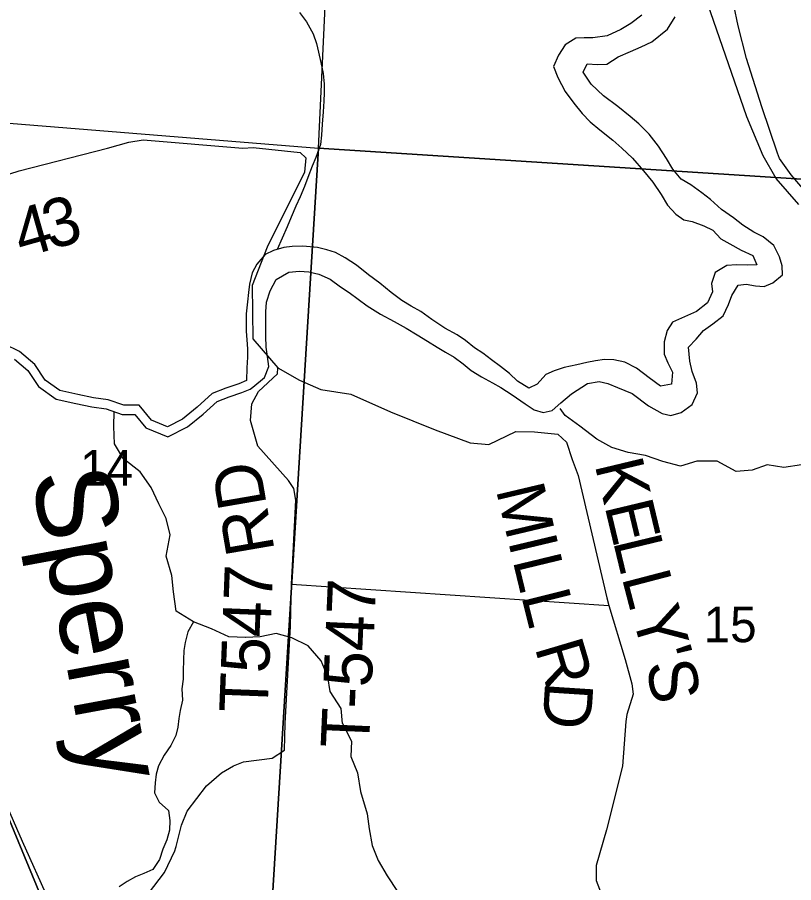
# Model space of a CAD drawing. Extents: x 0 to 82.7, y -0.2 to 22.
# Drawn here: x 3.348 to 4.26, y 16.567 to 17.584 of the extents above; entities that cross this region are included whole.
import ezdxf

# ---------------------------------------------------------------- set-up
doc = ezdxf.new("R2010")
doc.units = 0
for name, color, linetype in [('GM_X_County_Road', 7, 'Continuous'), ('GM_X_County_Road_Text', 7, 'Continuous'), ('GM_X_Minor_River', 7, 'Continuous'), ('GM_X_Minor_River_Text', 7, 'Continuous'), ('GM_X_Rail_Line', 7, 'Continuous'), ('GM_X_Section', 7, 'Continuous'), ('GM_X_Section_Text', 7, 'Continuous'), ('GM_X_State_Route', 7, 'Continuous'), ('GM_X_Township_Road', 7, 'Continuous'), ('GM_X_Township_Road_Text', 7, 'Continuous'), ('GM_X_Township_Text', 7, 'Continuous'), ('SH_Cut_Line', 7, 'Continuous')]:
    doc.layers.add(name, color=color, linetype=linetype)

msp = doc.modelspace()

# ---------------------------------------------------------------- linework, layer by layer
at = {"layer": 'GM_X_County_Road'}
for points in [[(3.3096, 17.3905), (3.3503, 17.4035), (3.454, 17.4299), (3.479, 17.4369), (3.4961, 17.4398), (3.6132, 17.4301), (3.6251, 17.4309), (3.6804, 17.4248), (3.6869, 17.4187), (3.6854, 17.4016), (3.6418, 17.3136), (3.624, 17.2688), (3.6248, 17.2062), (3.6543, 17.1721), (3.6797, 17.1577), (3.7047, 17.1467), (3.74, 17.141), (3.7866, 17.1205), (3.8389, 17.0993), (3.8802, 17.0841), (3.9018, 17.0818), (3.9336, 17.0974), (3.9556, 17.097), (3.9828, 17.094), (3.993, 17.0848), (3.9999, 17.0645), (4.0068, 17.0456), (4.0407, 16.9017)], [(4.0407, 16.9017), (4.0428, 16.893), (4.0621, 16.8294), (4.0699, 16.8008), (4.0713, 16.7889), (4.064, 16.765), (4.0629, 16.7567), (4.0589, 16.7041), (4.0403, 16.6296), (4.0279, 16.5877), (4.0281, 16.5698), (4.0357, 16.5496)]]:
    msp.add_lwpolyline(points, dxfattribs=at)
at = {"layer": 'GM_X_Minor_River'}
for points in [[(3.6796, 17.5893), (3.6879, 17.5782), (3.6958, 17.5641), (3.6996, 17.553), (3.7018, 17.5427), (3.7047, 17.5306), (3.7073, 17.5176), (3.7087, 17.5051), (3.7087, 17.4948), (3.7082, 17.4853), (3.7074, 17.4728), (3.7061, 17.458), (3.7053, 17.4451), (3.7041, 17.4341), (3.6987, 17.4189), (3.6944, 17.4087), (3.6894, 17.3954), (3.6855, 17.3848), (3.6805, 17.3727), (3.6751, 17.3617), (3.67, 17.3488), (3.665, 17.3374), (3.6592, 17.3242), (3.6532, 17.3111)], [(4.0818, 17.5863), (4.0689, 17.5764), (4.0571, 17.5692), (4.0408, 17.562), (4.024, 17.5597), (4.0138, 17.5597), (4.0043, 17.559), (3.9917, 17.5514), (3.9837, 17.5392), (3.978, 17.5259), (3.983, 17.513), (3.9917, 17.4967), (4.0016, 17.483), (4.0114, 17.4708), (4.0209, 17.4609), (4.0323, 17.4514), (4.0475, 17.4392), (4.0582, 17.4301), (4.0707, 17.4183), (4.0836, 17.4035), (4.0946, 17.3901), (4.1045, 17.3757), (4.1117, 17.3631), (4.1216, 17.3525), (4.1311, 17.346), (4.1406, 17.3437), (4.1546, 17.3388), (4.1649, 17.3335), (4.1744, 17.3236), (4.185, 17.3175), (4.1983, 17.3102), (4.212, 17.3038), (4.2166, 17.2931), (4.2055, 17.2927), (4.193, 17.2928), (4.1816, 17.292), (4.1679, 17.284), (4.1633, 17.2711), (4.1648, 17.2612), (4.1588, 17.2483), (4.1458, 17.2381), (4.1318, 17.232), (4.1177, 17.2255), (4.1112, 17.2157), (4.1078, 17.2027), (4.1078, 17.1879), (4.1123, 17.178), (4.1177, 17.167), (4.1165, 17.1529), (4.1036, 17.1503), (4.0903, 17.1602), (4.0755, 17.1716), (4.0618, 17.1785), (4.0489, 17.1815), (4.0378, 17.1819), (4.0272, 17.1804), (4.0169, 17.1781), (4.0052, 17.1755), (3.9903, 17.1724), (3.9785, 17.1683), (3.9687, 17.1641), (3.9588, 17.1527)], [(4.1366, 17.1961), (4.1454, 17.2056), (4.1541, 17.2159), (4.1651, 17.2235), (4.1773, 17.233), (4.1834, 17.2463), (4.1872, 17.2569), (4.1948, 17.2691), (4.2043, 17.2702), (4.215, 17.2683), (4.2252, 17.2675), (4.2355, 17.2717), (4.2469, 17.2812), (4.2465, 17.2918), (4.2435, 17.3025), (4.2367, 17.3158), (4.2241, 17.3257), (4.2131, 17.3314), (4.2002, 17.3394), (4.1892, 17.3481), (4.1751, 17.358), (4.1622, 17.3698), (4.152, 17.3774), (4.139, 17.387), (4.128, 17.3934), (4.1181, 17.4052), (4.1106, 17.4178), (4.1011, 17.4322), (4.0904, 17.4463), (4.0783, 17.4585), (4.068, 17.4672), (4.0536, 17.479), (4.0365, 17.4916), (4.0221, 17.5053), (4.0129, 17.5193), (4.0175, 17.5292), (4.0297, 17.5284), (4.0407, 17.5288), (4.054, 17.5372), (4.0684, 17.5436), (4.081, 17.5489), (4.0932, 17.555), (4.1118, 17.5698), (4.1209, 17.5842)], [(3.9588, 17.1527), (3.9489, 17.1481), (3.9356, 17.1565), (3.9261, 17.1653), (3.9158, 17.1736), (3.9052, 17.1813), (3.8949, 17.1892), (3.8851, 17.1953), (3.8744, 17.2041), (3.8646, 17.2106), (3.8501, 17.2186), (3.8349, 17.2288), (3.822, 17.2383), (3.8106, 17.2444), (3.7996, 17.2509), (3.7871, 17.2604), (3.7738, 17.2715), (3.7608, 17.2813), (3.7464, 17.2924), (3.7331, 17.3011), (3.7217, 17.3076), (3.7118, 17.3107), (3.7008, 17.3133), (3.6837, 17.3149), (3.6708, 17.3145), (3.6613, 17.3134), (3.6491, 17.3099), (3.6392, 17.305), (3.6293, 17.2936), (3.624, 17.2834), (3.621, 17.2704), (3.6198, 17.2606), (3.6187, 17.2495), (3.6171, 17.2355), (3.6171, 17.215), (3.6179, 17.2047), (3.6186, 17.1944), (3.6186, 17.1845), (3.6179, 17.172), (3.6172, 17.157)], [(3.6215, 17.1471), (3.6246, 17.1494), (3.6383, 17.1605), (3.6437, 17.1734), (3.6421, 17.1855), (3.6403, 17.1962), (3.6399, 17.2091), (3.6399, 17.2376), (3.641, 17.249), (3.6452, 17.2623), (3.6521, 17.2756), (3.6669, 17.2843), (3.6795, 17.2855), (3.6905, 17.2847), (3.7023, 17.282), (3.7156, 17.2763), (3.7277, 17.2672), (3.738, 17.2603), (3.7486, 17.2527), (3.7589, 17.2447), (3.7748, 17.2352), (3.7908, 17.2265), (3.8048, 17.2185), (3.8178, 17.2109), (3.8299, 17.2032), (3.8413, 17.1964), (3.8512, 17.1903), (3.8611, 17.1846), (3.8717, 17.1766), (3.8812, 17.169), (3.8934, 17.1614), (3.9063, 17.1542), (3.9162, 17.1488), (3.9294, 17.1401), (3.9446, 17.1298), (3.9553, 17.1226), (3.9659, 17.1195), (3.9762, 17.1218), (3.9865, 17.1309), (3.999, 17.1415), (4.018, 17.1537), (4.0317, 17.1559), (4.0416, 17.1537), (4.053, 17.1491), (4.0701, 17.1418), (4.0895, 17.1274), (4.1054, 17.1182), (4.1157, 17.116), (4.1278, 17.1194), (4.1408, 17.1289), (4.1469, 17.1425), (4.1457, 17.1539), (4.1408, 17.1676), (4.1381, 17.1798), (4.1366, 17.1961)], [(3.6172, 17.157), (3.6082, 17.1532), (3.5931, 17.1481), (3.5771, 17.1418), (3.5596, 17.1259), (3.5421, 17.1116), (3.5246, 17.1027), (3.5057, 17.1104), (3.4914, 17.128), (3.4732, 17.1281), (3.455, 17.1343), (3.4376, 17.1367), (3.4194, 17.1406), (3.3982, 17.1453), (3.3809, 17.1576), (3.3688, 17.1759), (3.3507, 17.1912), (3.3333, 17.1997)], [(3.3448, 17.1821), (3.3607, 17.1687), (3.3729, 17.15), (3.3938, 17.1353), (3.4171, 17.1301), (3.4357, 17.1261), (3.4525, 17.1237), (3.4714, 17.1173), (3.4862, 17.1172), (3.499, 17.1014), (3.5251, 17.0908), (3.548, 17.1026), (3.5666, 17.1177), (3.5829, 17.1324), (3.5968, 17.138), (3.612, 17.143), (3.6215, 17.1471)], [(3.616, 16.8555), (3.5967, 16.8561), (3.5763, 16.8654), (3.5551, 16.8739), (3.5347, 16.8862), (3.5318, 16.909), (3.5296, 16.928), (3.5229, 16.9508), (3.5276, 16.9758), (3.5232, 16.9949), (3.5142, 17.0124), (3.5052, 17.0314), (3.4924, 17.0497), (3.4728, 17.0651), (3.4623, 17.0826), (3.4617, 17.1031), (3.4618, 17.1206), (3.4618, 17.12)], [(4.2692, 17.0582), (4.2483, 17.0549), (4.229, 17.058), (4.2111, 17.0517), (4.1926, 17.0503), (4.1703, 17.0625), (4.1464, 17.0623), (4.127, 17.0567), (4.1062, 17.0621), (4.0861, 17.069), (4.0657, 17.0726), (4.0464, 17.0784), (4.0286, 17.0883), (4.009, 17.1036), (3.9916, 17.1162), (3.9856, 17.1241)], [(3.5551, 16.8739), (3.5483, 16.8621), (3.5453, 16.8496), (3.5437, 16.8402), (3.5433, 16.8292), (3.5428, 16.8159), (3.5428, 16.8064), (3.5416, 16.795), (3.5423, 16.7818), (3.5396, 16.7696), (3.538, 16.7602), (3.5368, 16.7499), (3.5345, 16.7401), (3.5284, 16.7284), (3.5208, 16.717), (3.5139, 16.7045), (3.5112, 16.6947), (3.51, 16.6845), (3.5092, 16.6727), (3.5148, 16.6621), (3.5257, 16.6521), (3.5275, 16.6404), (3.5271, 16.629), (3.5236, 16.6176), (3.5191, 16.6067), (3.5152, 16.5945), (3.5072, 16.5828), (3.4966, 16.5783), (3.4871, 16.5742), (3.4773, 16.5689), (3.4678, 16.5625)], [(3.7302, 16.7544), (3.7284, 16.7721), (3.7157, 16.7919), (3.7128, 16.809), (3.7049, 16.8281), (3.6899, 16.8456), (3.6706, 16.8548), (3.652, 16.8602), (3.6334, 16.8561), (3.616, 16.8555), (3.6164, 16.8559)], [(3.7302, 16.7544), (3.7405, 16.7336), (3.74, 16.7154), (3.7476, 16.6963), (3.7513, 16.6743), (3.7592, 16.6484), (3.7614, 16.6305), (3.7648, 16.6112), (3.7719, 16.5933), (3.7825, 16.5754), (3.7946, 16.5571)]]:
    msp.add_lwpolyline(points, dxfattribs=at)
at = {"layer": 'GM_X_Rail_Line'}
msp.add_lwpolyline([(4.266, 17.3638), (4.2395, 17.3944), (4.2242, 17.4209), (4.2049, 17.4668), (4.1341, 17.672)], dxfattribs=at)
at = {"layer": 'GM_X_Section'}
msp.add_lwpolyline([(3.7473, 18.3959), (3.7502, 18.459), (4.7658, 18.3936), (4.7026, 17.3656), (3.7019, 17.4301), (3.7258, 17.938)], dxfattribs=at)
for points in [[(2.9797, 17.4884), (3.7019, 17.4301), (3.6383, 16.3983), (3.4469, 16.4092), (3.3543, 16.6156), (3.1437, 17.0983)], [(3.7019, 17.4301), (4.7026, 17.3656), (4.6367, 16.3423), (3.6383, 16.3983)]]:
    msp.add_lwpolyline(points, close=True, dxfattribs=at)
at = {"layer": 'GM_X_State_Route'}
msp.add_lwpolyline([(4.2752, 17.3777), (4.2569, 17.3988), (4.2435, 17.4178), (4.2411, 17.4243), (4.2226, 17.4784), (4.2045, 17.5352), (4.1946, 17.5735), (4.1895, 17.598)], dxfattribs=at)
at = {"layer": 'GM_X_Township_Road'}
msp.add_line((3.6703, 16.9179), (4.0428, 16.893), dxfattribs=at)
for points in [[(3.6721, 16.9549), (3.6752, 17.0165), (3.6729, 17.0302), (3.6665, 17.0397), (3.6305, 17.0799), (3.6221, 17.1103), (3.6236, 17.1296), (3.6316, 17.1444), (3.6536, 17.1649), (3.6543, 17.1721)], [(3.5342, 16.6085), (3.5346, 16.61), (3.5409, 16.6349), (3.5478, 16.6512), (3.5702, 16.6812), (3.5881, 16.6963), (3.6021, 16.7047), (3.6139, 16.7092), (3.6476, 16.7136), (3.6618, 16.7229), (3.6626, 16.7544), (3.6689, 16.8686), (3.6703, 16.9179), (3.6721, 16.9549)], [(3.4073, 16.4755), (3.4373, 16.4734), (3.4536, 16.476), (3.4639, 16.4817), (3.4696, 16.4904), (3.4734, 16.5128), (3.4833, 16.528), (3.4959, 16.5466), (3.521, 16.5795), (3.5332, 16.6046), (3.5342, 16.6085)]]:
    msp.add_lwpolyline(points, dxfattribs=at)
at = {"layer": 'GM_X_Township_Text'}
msp.add_lwpolyline([(5.9672, 20.3493), (3.6288, 20.5056), (3.179, 20.5374), (2.884, 20.5583), (2.8651, 20.279), (2.8645, 20.2703), (2.8645, 20.2693), (2.8288, 19.7415), (2.7788, 19.0007), (2.7784, 18.9951), (2.7199, 18.1299), (3.0279, 17.3486), (3.0556, 17.2782), (3.2909, 16.7562), (3.4071, 16.476), (3.6125, 15.9807), (3.8036, 15.5496), (4.1209, 14.8338)], dxfattribs=at)
msp.add_lwpolyline([(2.1, 19.5964), (2.1, 14.1), (2.4652, 14.1), (3.1288, 14.3932), (3.6092, 14.6054), (3.7187, 14.6543), (4.1209, 14.8338), (3.8036, 15.5496), (3.6125, 15.9807), (3.4071, 16.476), (3.2909, 16.7562), (3.0556, 17.2782), (3.0279, 17.3486), (2.7199, 18.1299), (2.4438, 18.782), (2.397, 18.8926), (2.3145, 19.0873), (2.2742, 19.1826)], close=True, dxfattribs=at)
at = {"layer": 'SH_Cut_Line'}
for points in [[(4.1209, 14.8338), (3.8036, 15.5496), (3.6125, 15.9807), (3.4071, 16.476), (3.2909, 16.7562), (3.0556, 17.2782), (3.0279, 17.3486), (2.7199, 18.1299), (2.7784, 18.9951), (2.7788, 19.0007), (2.8288, 19.7415), (2.8645, 20.2693), (2.8645, 20.2703), (2.8651, 20.279), (2.884, 20.5583), (3.179, 20.5374), (3.6288, 20.5056), (5.9672, 20.3493), (5.9756, 20.3782), (6.1272, 20.9), (2.1, 20.9), (2.1, 14.1)], [(8.9, 14.1), (8.9, 20.9), (6.1272, 20.9), (5.9756, 20.3782), (5.9672, 20.3493), (3.6288, 20.5056), (3.179, 20.5374), (2.884, 20.5583), (2.8651, 20.279), (2.8645, 20.2703), (2.8645, 20.2693), (2.8288, 19.7415), (2.7788, 19.0007), (2.7784, 18.9951), (2.7199, 18.1299), (3.0279, 17.3486), (3.0556, 17.2782), (3.2909, 16.7562), (3.4071, 16.476), (3.6125, 15.9807), (3.8036, 15.5496), (4.1209, 14.8338)]]:
    msp.add_lwpolyline(points, dxfattribs=at)

# ---------------------------------------------------------------- texts
at = {"layer": 'GM_X_County_Road_Text'}
for s, rotation, p in [('3', 15.9617, (3.3871, 17.3104)), ('4', 15.8275, (3.3532, 17.3008)), ('K', 283.4743, (4.026, 17.0586)), ('M', 283.3313, (3.91, 17.0292)), ('E', 283.4692, (4.0376, 17.01)), ('I', 283.3898, (3.9243, 16.9691)), ('L', 283.583, (4.0476, 16.9685)), ('L', 283.5846, (3.9297, 16.9462)), ('L', 284.6517, (4.0578, 16.9261)), ('L', 284.1107, (3.9398, 16.9044)), ('Y', 286.3844, (4.0691, 16.8831)), ('R', 286.544, (3.9555, 16.8438)), ("'", 286.2757, (4.0832, 16.8352)), ('S', 280.6232, (4.0863, 16.8246)), ('D', 266.2854, (3.9682, 16.8043))]:
    msp.add_text(s, height=0.0568, rotation=rotation, dxfattribs=at).set_placement(p)
at = {"layer": 'GM_X_Minor_River_Text'}
msp.add_text('Sperry', height=0.09468, rotation=280.4936, dxfattribs=at).set_placement((3.3643, 17.0468))
at = {"layer": 'GM_X_Section_Text'}
for s, p in [('14', (3.4218, 17.0337)), ('15', (4.1542, 16.8498))]:
    msp.add_text(s, height=0.04186, rotation=0, dxfattribs=at).set_placement(p)
at = {"layer": 'GM_X_Township_Road_Text'}
for s, rotation, p in [('RD', 99.7986, (3.6506, 16.9571)), ('T547', 87.7828, (3.642, 16.7663)), ('T-547', 87.4786, (3.7611, 16.7245))]:
    msp.add_text(s, height=0.05682, rotation=rotation, dxfattribs=at).set_placement(p)

doc.saveas('drawing.dxf')
